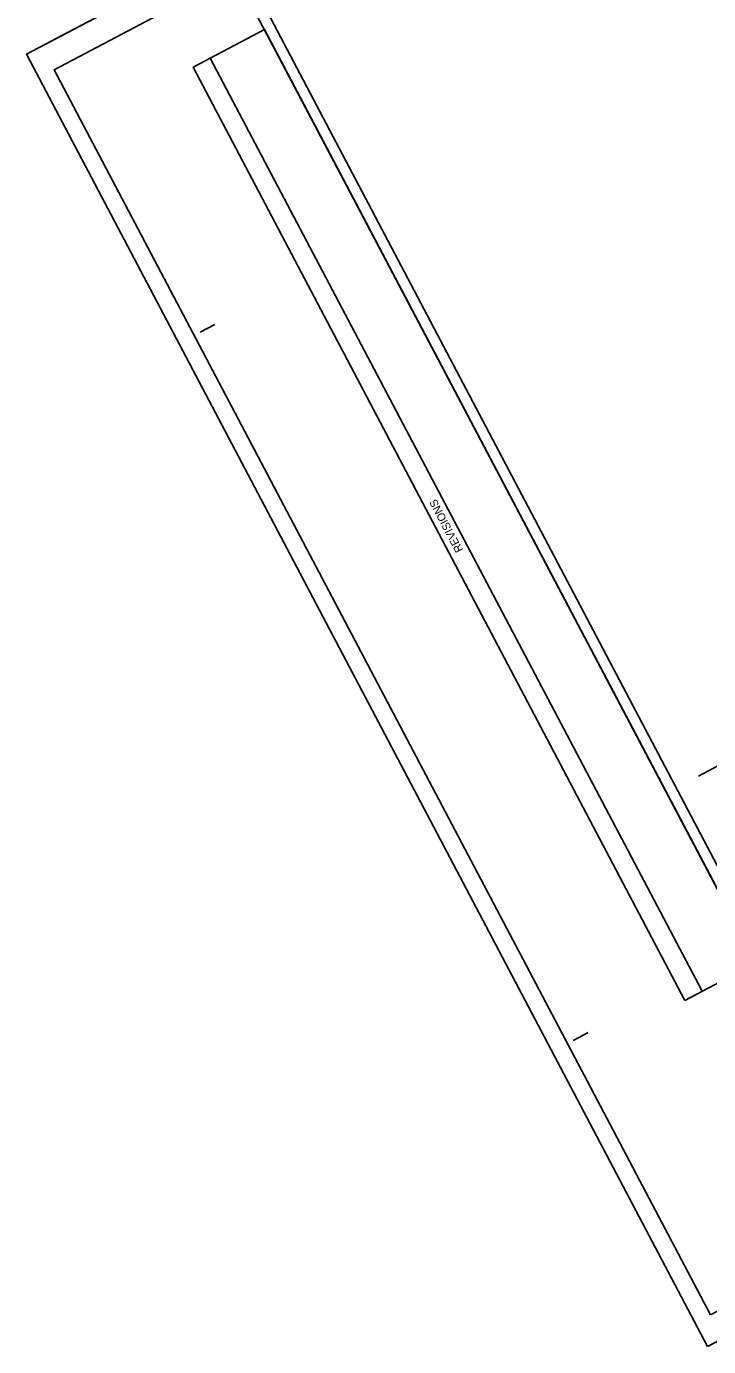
# Model space of a CAD drawing. Extents: x 1380651 to 1383136, y 594581 to 596344.
# Drawn here: x 1380651 to 1381162, y 594581 to 595571 of the extents above; entities that cross this region are included whole.
import ezdxf

# ---------------------------------------------------------------- set-up
doc = ezdxf.new("R2010")
doc.units = 0
for name, color, linetype in [('Prop Horizontal Alignment Curve and Spiral Data', 7, 'Continuous'), ('Sheet Block Revision CELL', 7, 'Continuous'), ('Sheet Clip Boundary CELL', 7, 'Continuous'), ('Sheet Cutting Line CELL', 7, 'Continuous'), ('Sheet Layout Plan Border', 7, 'Continuous'), ('Sheet Plan CELL', 7, 'Continuous'), ('Sheet Plot Border Inside CELL', 7, 'Continuous'), ('Sheet Plot Border Outside CELL', 7, 'Continuous')]:
    doc.layers.add(name, color=color, linetype=linetype)

msp = doc.modelspace()

# ---------------------------------------------------------------- linework, layer by layer
at = {"layer": 'Prop Horizontal Alignment Curve and Spiral Data'}
msp.add_line((1381154.62, 595009.14), (1381352.46, 595113.44), dxfattribs=at)
at = {"layer": 'Sheet Block Revision CELL'}
msp.add_line((1381157.29, 594847.76), (1380788.57, 595547.15), dxfattribs=at)
msp.add_lwpolyline([(1381144.43, 594840.95), (1380775.71, 595540.36), (1380829.25, 595568.61), (1381197.97, 594869.2)], close=True, dxfattribs=at)
at = {"layer": 'Sheet Clip Boundary CELL'}
msp.add_lwpolyline([(1381254.23, 594780.01), (1382566.26, 595471.7), (1382154.39, 596252.97), (1381978.55, 596160.27), (1381909.21, 596291.79), (1380773.01, 595692.8)], close=True, dxfattribs=at)
at = {"layer": 'Sheet Cutting Line CELL'}
for p, q in [((1382140.02, 596335.19), (1380650.8, 595550.09)), ((1380650.8, 595550.09), (1381161.45, 594581.45)), ((1381161.45, 594581.45), (1382650.68, 595366.55))]:
    msp.add_line(p, q, dxfattribs=at)
at = {"layer": 'Sheet Layout Plan Border'}
msp.add_lwpolyline([(1381298.21, 594679), (1382625.14, 595378.54), (1382205.45, 596174.64), (1382028.49, 596081.35), (1381958.53, 596214.06), (1380808.55, 595607.8)], close=True, dxfattribs=at)
at = {"layer": 'Sheet Plan CELL'}
for p, q in [((1380780.97, 595341.74), (1380792.03, 595347.6)), ((1381060.8, 594811), (1381071.86, 594816.82))]:
    msp.add_line(p, q, dxfattribs=at)
for points in [[(1382135.49, 596307.38), (1380808.56, 595607.84), (1381298.23, 594679.01), (1382625.14, 595378.54)], [(1381298.23, 594679.01), (1380808.55, 595607.8), (1381958.5, 596214.09), (1382028.49, 596081.35), (1382205.45, 596174.63), (1382625.14, 595378.54)]]:
    msp.add_lwpolyline(points, close=True, dxfattribs=at)
at = {"layer": 'Sheet Plot Border Inside CELL'}
msp.add_lwpolyline([(1381163.62, 594605.21), (1382637.35, 595382.15), (1382145.37, 596315.4), (1380671.62, 595538.46)], close=True, dxfattribs=at)
at = {"layer": 'Sheet Plot Border Outside CELL'}
msp.add_lwpolyline([(1381161.45, 594581.45), (1382650.68, 595366.55), (1382140.02, 596335.19), (1380650.8, 595550.09)], close=True, dxfattribs=at)

# ---------------------------------------------------------------- texts
at = {"layer": 'Sheet Block Revision CELL'}
msp.add_text('REVISIONS', height=6, rotation=117.7977, dxfattribs=at).set_placement((1380978.29, 595178.61))

doc.saveas('drawing.dxf')
